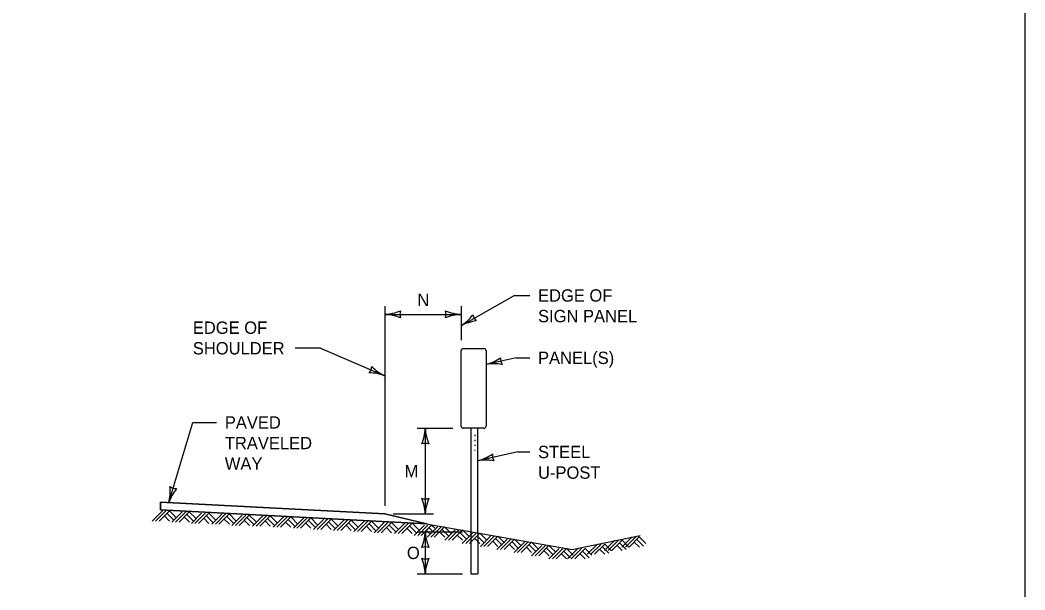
# Model space of a CAD drawing. Extents: x 49991.4 to 50021, y 49987.6 to 50011.4.
# Drawn here: x 50011.868 to 50016.75, y 49993.612 to 49996.379 of the extents above; entities that cross this region are included whole.
import ezdxf

# ---------------------------------------------------------------- set-up
doc = ezdxf.new("R2010")
doc.units = 0
for name, color, linetype in [('Level 1', 7, 'Continuous'), ('Level 2', 7, 'Continuous'), ('Level 3', 7, 'Continuous'), ('Level 4', 7, 'Continuous')]:
    doc.layers.add(name, color=color, linetype=linetype)

msp = doc.modelspace()

# ---------------------------------------------------------------- linework, layer by layer
at = {"layer": 'Level 1'}
for p, q in [((50014.0213, 49994.7842), (50014.1209, 49994.7842)), ((50014.0103, 49994.4079), (50014.0103, 49994.7732)), ((50014.1321, 49994.7732), (50014.1321, 49994.4079)), ((50014.1209, 49994.3968), (50014.0213, 49994.3968)), ((50014.0581, 49994.3968), (50014.0581, 49993.8946)), ((50014.0921, 49993.8886), (50014.092, 49994.3968)), ((50012.5497, 49994.0381), (50013.64, 49993.981)), ((50012.5497, 49994.001), (50012.5497, 49994.0381)), ((50013.64, 49993.981), (50012.5497, 49994.0381)), ((50012.5497, 49994.0381), (50012.5497, 49994.001)), ((50013.843, 49993.9332), (50012.5497, 49994.001)), ((50012.5497, 49994.001), (50013.843, 49993.9332)), ((50012.5092, 49993.9464), (50012.5592, 49993.9964)), ((50012.5267, 49993.9464), (50012.5767, 49993.9964)), ((50012.5442, 49993.9464), (50012.5942, 49993.9964)), ((50012.5695, 49993.9716), (50012.5947, 49993.9464)), ((50012.5819, 49993.984), (50012.6144, 49993.9515)), ((50012.5942, 49993.9964), (50012.6267, 49993.9639)), ((50012.6053, 49993.9414), (50012.6553, 49993.9914)), ((50012.6228, 49993.9414), (50012.6728, 49993.9914)), ((50012.6403, 49993.9414), (50012.6903, 49993.9914)), ((50012.6656, 49993.9666), (50012.6908, 49993.9414)), ((50012.678, 49993.979), (50012.7105, 49993.9465)), ((50012.6903, 49993.9914), (50012.7228, 49993.9589)), ((50012.7001, 49993.9352), (50012.7501, 49993.9852)), ((50012.7176, 49993.9352), (50012.7676, 49993.9852)), ((50012.7351, 49993.9352), (50012.7851, 49993.9852)), ((50012.7604, 49993.9604), (50012.7856, 49993.9352)), ((50012.7728, 49993.9728), (50012.8053, 49993.9403)), ((50012.7851, 49993.9852), (50012.8176, 49993.9527)), ((50012.7992, 49993.9309), (50012.8492, 49993.9809)), ((50012.8167, 49993.9309), (50012.8667, 49993.9809)), ((50012.8342, 49993.9309), (50012.8842, 49993.9809)), ((50012.8595, 49993.9561), (50012.8847, 49993.9309)), ((50012.8719, 49993.9685), (50012.9044, 49993.936)), ((50012.8842, 49993.9809), (50012.9167, 49993.9484)), ((50012.8968, 49993.9257), (50012.9468, 49993.9757)), ((50012.9143, 49993.9257), (50012.9643, 49993.9757)), ((50012.9318, 49993.9257), (50012.9818, 49993.9757)), ((50012.9571, 49993.9509), (50012.9823, 49993.9257)), ((50012.9695, 49993.9633), (50013.002, 49993.9308)), ((50012.9818, 49993.9757), (50013.0143, 49993.9432)), ((50012.9977, 49993.9217), (50013.0477, 49993.9717)), ((50013.0152, 49993.9217), (50013.0652, 49993.9717)), ((50013.0327, 49993.9217), (50013.0827, 49993.9717)), ((50013.0704, 49993.9593), (50013.1029, 49993.9268)), ((50013.0827, 49993.9717), (50013.1152, 49993.9392)), ((50013.0978, 49993.9163), (50013.1478, 49993.9663)), ((50013.1153, 49993.9163), (50013.1653, 49993.9663)), ((50013.1328, 49993.9163), (50013.1828, 49993.9663)), ((50013.1705, 49993.9539), (50013.203, 49993.9214)), ((50013.1828, 49993.9663), (50013.2153, 49993.9338)), ((50013.1959, 49993.9115), (50013.2459, 49993.9615)), ((50013.2134, 49993.9115), (50013.2634, 49993.9615)), ((50013.2309, 49993.9115), (50013.2809, 49993.9615)), ((50013.2686, 49993.9491), (50013.3011, 49993.9166)), ((50013.2809, 49993.9615), (50013.3134, 49993.929)), ((50013.2943, 49993.9056), (50013.3443, 49993.9556)), ((50013.3118, 49993.9056), (50013.3618, 49993.9556)), ((50013.3293, 49993.9056), (50013.3793, 49993.9556)), ((50013.3793, 49993.9556), (50013.4118, 49993.9231)), ((50013.3915, 49993.9006), (50013.4415, 49993.9506)), ((50013.409, 49993.9006), (50013.459, 49993.9506)), ((50013.4265, 49993.9006), (50013.4765, 49993.9506)), ((50013.4765, 49993.9506), (50013.509, 49993.9181)), ((50013.64, 49993.981), (50013.8581, 49993.9298)), ((50013.843, 49993.9333), (50013.64, 49993.981)), ((50013.058, 49993.9469), (50013.0832, 49993.9217)), ((50013.1581, 49993.9415), (50013.1833, 49993.9163)), ((50013.2562, 49993.9367), (50013.2814, 49993.9115)), ((50013.3546, 49993.9308), (50013.3798, 49993.9056)), ((50013.367, 49993.9432), (50013.3995, 49993.9107)), ((50013.4518, 49993.9258), (50013.477, 49993.9006)), ((50013.4642, 49993.9382), (50013.4967, 49993.9057)), ((50013.4901, 49993.8963), (50013.5401, 49993.9463)), ((50013.5076, 49993.8963), (50013.5576, 49993.9463)), ((50013.5251, 49993.8963), (50013.5751, 49993.9463)), ((50013.5504, 49993.9215), (50013.5756, 49993.8963)), ((50013.5628, 49993.9339), (50013.5953, 49993.9014)), ((50013.5751, 49993.9463), (50013.6076, 49993.9138)), ((50013.5877, 49993.8899), (50013.6377, 49993.9399)), ((50013.6052, 49993.8899), (50013.6552, 49993.9399)), ((50013.6227, 49993.8899), (50013.6727, 49993.9399)), ((50013.648, 49993.9151), (50013.6732, 49993.8899)), ((50013.6604, 49993.9275), (50013.6929, 49993.895)), ((50013.6727, 49993.9399), (50013.7052, 49993.9074)), ((50013.6877, 49993.8859), (50013.7377, 49993.9359)), ((50013.7052, 49993.8859), (50013.7552, 49993.9359)), ((50013.7227, 49993.8859), (50013.7727, 49993.9359)), ((50013.748, 49993.9111), (50013.7732, 49993.8859)), ((50013.7604, 49993.9235), (50013.7929, 49993.891)), ((50013.7727, 49993.9359), (50013.8052, 49993.9034)), ((50013.7824, 49993.8763), (50013.8324, 49993.9263)), ((50013.7999, 49993.8763), (50013.8499, 49993.9263)), ((50013.8174, 49993.8763), (50013.8674, 49993.9263)), ((50013.8427, 49993.9015), (50013.8579, 49993.8863)), ((50013.843, 49993.9332), (50013.843, 49993.9333)), ((50013.8456, 49993.8685), (50013.8956, 49993.9185)), ((50013.8551, 49993.9139), (50013.8702, 49993.8988)), ((50013.8581, 49993.9298), (50014.5505, 49993.8078)), ((50013.8631, 49993.8685), (50013.9131, 49993.9185)), ((50013.8674, 49993.9263), (50013.8824, 49993.9113)), ((50013.8806, 49993.8685), (50013.9306, 49993.9185)), ((50013.9183, 49993.9061), (50013.9508, 49993.8736)), ((50013.9306, 49993.9185), (50013.9631, 49993.886)), ((50013.9319, 49993.8536), (50013.9819, 49993.9036)), ((50013.9494, 49993.8536), (50013.9994, 49993.9036)), ((50013.9669, 49993.8536), (50014.0169, 49993.9036)), ((50014.0169, 49993.9036), (50014.0494, 49993.8711)), ((50013.9059, 49993.8937), (50013.9311, 49993.8685)), ((50013.9922, 49993.8788), (50014.0174, 49993.8536)), ((50014.0046, 49993.8912), (50014.0371, 49993.8587)), ((50014.0167, 49993.8372), (50014.0667, 49993.8872)), ((50014.0342, 49993.8372), (50014.0842, 49993.8872)), ((50014.0517, 49993.8372), (50014.1017, 49993.8872)), ((50014.077, 49993.8624), (50014.1022, 49993.8372)), ((50014.0894, 49993.8748), (50014.1219, 49993.8423)), ((50014.1017, 49993.8872), (50014.1342, 49993.8547)), ((50014.1044, 49993.8238), (50014.1544, 49993.8738)), ((50014.1219, 49993.8238), (50014.1719, 49993.8738)), ((50014.1394, 49993.8238), (50014.1894, 49993.8738)), ((50014.1771, 49993.8614), (50014.2096, 49993.8289)), ((50014.1847, 49993.8089), (50014.2347, 49993.8589)), ((50014.1894, 49993.8738), (50014.2219, 49993.8413)), ((50014.2022, 49993.8089), (50014.2522, 49993.8589)), ((50014.2197, 49993.8089), (50014.2697, 49993.8589)), ((50014.2697, 49993.8589), (50014.3022, 49993.8264)), ((50014.5505, 49993.8078), (50014.8813, 49993.8765)), ((50014.7083, 49993.803), (50014.7583, 49993.853)), ((50014.7258, 49993.803), (50014.7758, 49993.853)), ((50014.7433, 49993.803), (50014.7933, 49993.853)), ((50014.7916, 49993.8193), (50014.8416, 49993.8693)), ((50014.7933, 49993.853), (50014.8258, 49993.8205)), ((50014.8091, 49993.8193), (50014.8591, 49993.8693)), ((50014.8266, 49993.8193), (50014.8766, 49993.8693)), ((50014.8643, 49993.8569), (50014.8968, 49993.8244)), ((50014.8766, 49993.8693), (50014.9091, 49993.8368)), ((50014.1647, 49993.849), (50014.1899, 49993.8238)), ((50014.245, 49993.8341), (50014.2702, 49993.8089)), ((50014.2574, 49993.8465), (50014.2899, 49993.814)), ((50014.268, 49993.7941), (50014.318, 49993.8441)), ((50014.2855, 49993.7941), (50014.3355, 49993.8441)), ((50014.303, 49993.7941), (50014.353, 49993.8441)), ((50014.3283, 49993.8193), (50014.3535, 49993.7941)), ((50014.3407, 49993.8317), (50014.3732, 49993.7992)), ((50014.3528, 49993.7777), (50014.4028, 49993.8277)), ((50014.353, 49993.8441), (50014.3855, 49993.8116)), ((50014.3703, 49993.7777), (50014.4203, 49993.8277)), ((50014.3878, 49993.7777), (50014.4378, 49993.8277)), ((50014.4131, 49993.8029), (50014.4383, 49993.7777)), ((50014.4255, 49993.8153), (50014.458, 49993.7828)), ((50014.4375, 49993.7628), (50014.4875, 49993.8128)), ((50014.4378, 49993.8277), (50014.4703, 49993.7952)), ((50014.455, 49993.7628), (50014.505, 49993.8128)), ((50014.4725, 49993.7628), (50014.5225, 49993.8128)), ((50014.5225, 49993.8128), (50014.555, 49993.7803)), ((50014.5283, 49993.7628), (50014.5783, 49993.8128)), ((50014.5458, 49993.7628), (50014.5958, 49993.8128)), ((50014.5633, 49993.7628), (50014.6133, 49993.8128)), ((50014.6133, 49993.8128), (50014.6458, 49993.7803)), ((50014.6235, 49993.7851), (50014.6735, 49993.8351)), ((50014.641, 49993.7851), (50014.691, 49993.8351)), ((50014.6585, 49993.7851), (50014.7085, 49993.8351)), ((50014.6838, 49993.8103), (50014.709, 49993.7851)), ((50014.6962, 49993.8227), (50014.7287, 49993.7902)), ((50014.7085, 49993.8351), (50014.741, 49993.8026)), ((50014.7686, 49993.8282), (50014.7938, 49993.803)), ((50014.781, 49993.8406), (50014.8135, 49993.8081)), ((50014.8519, 49993.8445), (50014.8771, 49993.8193)), ((50014.4978, 49993.788), (50014.523, 49993.7628)), ((50014.5102, 49993.8004), (50014.5427, 49993.7679)), ((50014.5886, 49993.788), (50014.6138, 49993.7628)), ((50014.601, 49993.8004), (50014.6335, 49993.7679))]:
    msp.add_line(p, q, dxfattribs=at)
msp.add_lwpolyline([(49999.3835, 49998.9992), (50016.7501, 49998.9992), (50016.7501, 49987.7988), (49999.3835, 49987.7988)], close=True, dxfattribs=at)
for centre, start, end in [((50014.0214, 49994.7731), 90, 180), ((50014.121, 49994.7731), 0, 90), ((50014.0214, 49994.4079), 180, 270), ((50014.121, 49994.4079), 270, 0)]:
    msp.add_arc(centre, 0.0111, start, end, dxfattribs=at)
at = {"layer": 'Level 3'}
for p, q in [((50014.2705, 49995.0418), (50014.0103, 49994.8949)), ((50014.2705, 49995.0418), (50014.3446, 49995.0418)), ((50013.64, 49994.9902), (50013.64, 49994.021)), ((50014.0103, 49994.9902), (50014.0103, 49994.8242)), ((50013.64, 49994.9502), (50014.0103, 49994.9502)), ((50013.327, 49994.7855), (50013.2047, 49994.7855)), ((50013.327, 49994.7855), (50013.64, 49994.6519)), ((50014.2789, 49994.739), (50014.1321, 49994.7067)), ((50014.2789, 49994.739), (50014.3446, 49994.739)), ((50012.5903, 49994.036), (50012.7075, 49994.4254)), ((50012.7075, 49994.4254), (50012.8228, 49994.4254)), ((50013.7968, 49994.3968), (50013.9703, 49994.3968)), ((50013.8368, 49994.3968), (50013.8368, 49993.981)), ((50014.2857, 49994.2819), (50014.0921, 49994.2394)), ((50014.2857, 49994.2819), (50014.3446, 49994.2819)), ((50013.68, 49993.981), (50013.8768, 49993.981)), ((50013.7968, 49993.8946), (50014.0181, 49993.8946)), ((50013.8368, 49993.8946), (50013.8368, 49993.6895)), ((50013.7968, 49993.6895), (50014.0181, 49993.6895))]:
    msp.add_line(p, q, dxfattribs=at)
for centre, radius, start, end in [((50013.6285, 49995.1829), 0.233, 272.8273, 292.0772), ((50013.6309, 49994.7281), 0.2223, 67.456, 87.6395), ((50013.7682, 49994.9502), 0.0548, 162.1388, 197.8612), ((50014.0195, 49995.1724), 0.2223, 247.456, 267.6395), ((50013.8821, 49994.9502), 0.0548, 342.1388, 17.8612), ((50014.0218, 49994.7175), 0.233, 92.8273, 112.0772), ((50013.8846, 49995.0911), 0.233, 302.6479, 321.8977), ((50014.1216, 49994.9587), 0.0548, 191.9594, 227.6817), ((50014.1128, 49994.6976), 0.2223, 97.2766, 117.4601), ((50014.0709, 49994.9315), 0.233, 285.2379, 304.4877), ((50014.2573, 49994.7343), 0.0548, 174.5494, 210.2718), ((50013.5221, 49994.7022), 0.0548, 319.0178, 354.7402), ((50013.7357, 49994.8526), 0.2223, 224.335, 244.5185), ((50014.1709, 49994.4878), 0.2223, 79.8666, 100.0501), ((50013.5592, 49994.4333), 0.233, 69.7063, 88.9561), ((50013.6147, 49994.406), 0.2223, 337.456, 357.6395), ((50014.0695, 49994.4083), 0.233, 182.8273, 202.0772), ((50013.8368, 49994.2686), 0.0548, 72.1388, 107.8612), ((50014.031, 49994.4642), 0.233, 285.2168, 304.4667), ((50014.1308, 49994.0204), 0.2223, 79.8455, 100.029), ((50014.2174, 49994.2669), 0.0548, 174.5283, 210.2507), ((50012.3642, 49994.092), 0.233, 346.0786, 5.3285), ((50012.8004, 49993.9632), 0.2223, 140.7073, 160.8909), ((50012.6273, 49994.1588), 0.0548, 235.3902, 271.1125), ((50013.8368, 49994.1092), 0.0548, 252.1388, 287.8612), ((50013.6041, 49993.9695), 0.233, 2.8273, 22.0772), ((50014.059, 49993.9719), 0.2223, 157.456, 177.6395), ((50013.6147, 49993.9038), 0.2223, 337.456, 357.6395), ((50014.0695, 49993.9061), 0.233, 182.8273, 202.0772), ((50013.8368, 49993.7664), 0.0548, 72.1388, 107.8612), ((50013.8368, 49993.8177), 0.0548, 252.1388, 287.8612), ((50013.6041, 49993.678), 0.233, 2.8273, 22.0772), ((50014.059, 49993.6804), 0.2223, 157.456, 177.6395)]:
    msp.add_arc(centre, radius, start, end, dxfattribs=at)
at = {"layer": 'Level 4'}
for p, q in [((50014.0581, 49993.8946), (50014.0581, 49993.6895)), ((50014.0921, 49993.8886), (50014.0921, 49993.6895)), ((50014.0581, 49993.6895), (50014.0921, 49993.6895))]:
    msp.add_line(p, q, dxfattribs=at)

# ---------------------------------------------------------------- texts
at = {"layer": 'Level 1'}
for p in [(50014.0685, 49994.3338), (50014.0686, 49994.358), (50014.0682, 49994.2859), (50014.0687, 49994.3104)]:
    msp.add_text('.', height=0.05, dxfattribs=at).set_placement(p)
at = {"layer": 'Level 2'}
for s, p in [('EDGE OF', (50014.3846, 49995.0118)), ('N', (50013.7981, 49994.9902)), ('SIGN PANEL', (50014.3846, 49994.9118)), ('EDGE OF', (50012.7074, 49994.8555)), ('SHOULDER', (50012.7074, 49994.7555)), ('PANEL(S)', (50014.3846, 49994.709)), ('PAVED', (50012.8628, 49994.3954)), ('TRAVELED', (50012.8628, 49994.2954)), ('STEEL', (50014.3846, 49994.2519)), ('WAY', (50012.8628, 49994.1954)), ('M', (50013.7358, 49994.1589)), ('U-POST', (50014.3846, 49994.1519)), ('O', (50013.7474, 49993.7621))]:
    msp.add_text(s, height=0.06, dxfattribs=at).set_placement(p)

doc.saveas('drawing.dxf')
